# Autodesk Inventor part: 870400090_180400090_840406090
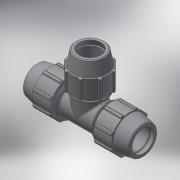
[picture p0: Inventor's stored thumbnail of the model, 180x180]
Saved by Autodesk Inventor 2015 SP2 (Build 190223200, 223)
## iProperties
Created: 2017-02
Part Number: 870400090_180400090_840406090
Material: Generic
Description: PLASSON TEE 90-90-90
Document SubType Name: Modeling
Designer: KIM
Mass: 2642.84 g
Surface Area: 3396.39 cm^2
Volume: 2642.84 cm^3
Density: 1 g/cm^3
Appearance: Default
Author: KIM
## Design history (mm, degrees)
derived "87040.ipt"
feature "Solid1::87040.ipt"
tag "TaggingFeature1"
body "Solid1"
other parameters: "d4" = 18.25, "d5" = 54.75, "d7" = 152, "d13" = 120 deg, "d14" = 117, "d15" = 10 deg, "d18" = 4.5, "d19" = 35 deg, "d20" = 17.5 deg, "d21" = 141.36, "d23" = 0, "d25" = 360 deg, "d27" = 3.04, "d42" = 76.65, "d43" = 4.56, "d46" = 2.7, "d63" = 164, "d67" = 114, "d77" = 152, "d78" = 10 deg, "d79" = 219, "d80" = 120 deg, "d81" = 117, "d82" = 18.25, "d85" = 114, "d87" = 7.3, "d88" = 7.3, "d89" = 54.75, "d90" = 76.65, "d98" = 141.36, "d99" = 35 deg, "d100" = 17.5 deg, "d102" = 0, "d103" = 3.04, "d107" = 360 deg, "d109" = 2.7, "d112" = 4.5, "d118" = 360 deg, "d121" = 0, "d128" = 438, "d131" = 81, "d132" = 81, "d133" = 164, "d134" = 3.28, "d152" = 0, "d154" = 0, "d156" = 0, "d158" = 0, "d163" = 16.3, "d165" = 17.94, "d166" = 108.3, "d167" = 108.3, "d168" = 5.98, "d169" = 125.4, "d170" = 2.99, "d171" = 4.485, "d172" = 125.4, "d173" = 5.43333, "d174" = 2.71667, "d175" = 4.075, "d176" = 1.8, "d177" = 4.5, "E_" = 152, "A_" = 219, "l_" = 164, "H_" = 438, "d162" = 32.6, "d164" = 35.88
